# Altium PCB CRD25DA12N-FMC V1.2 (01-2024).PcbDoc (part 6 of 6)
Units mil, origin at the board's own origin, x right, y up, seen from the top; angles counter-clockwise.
Board outline 8000 x 8000 mil, 6 copper layers (Top Layer, Layer 2, Layer 3, Layer 4, Layer 5, Bottom Layer), stack 91 mil thick; 574 components, 325 nets, 1631 pads, 633 vias.
Unrouted connection lines stored in the file: 1.
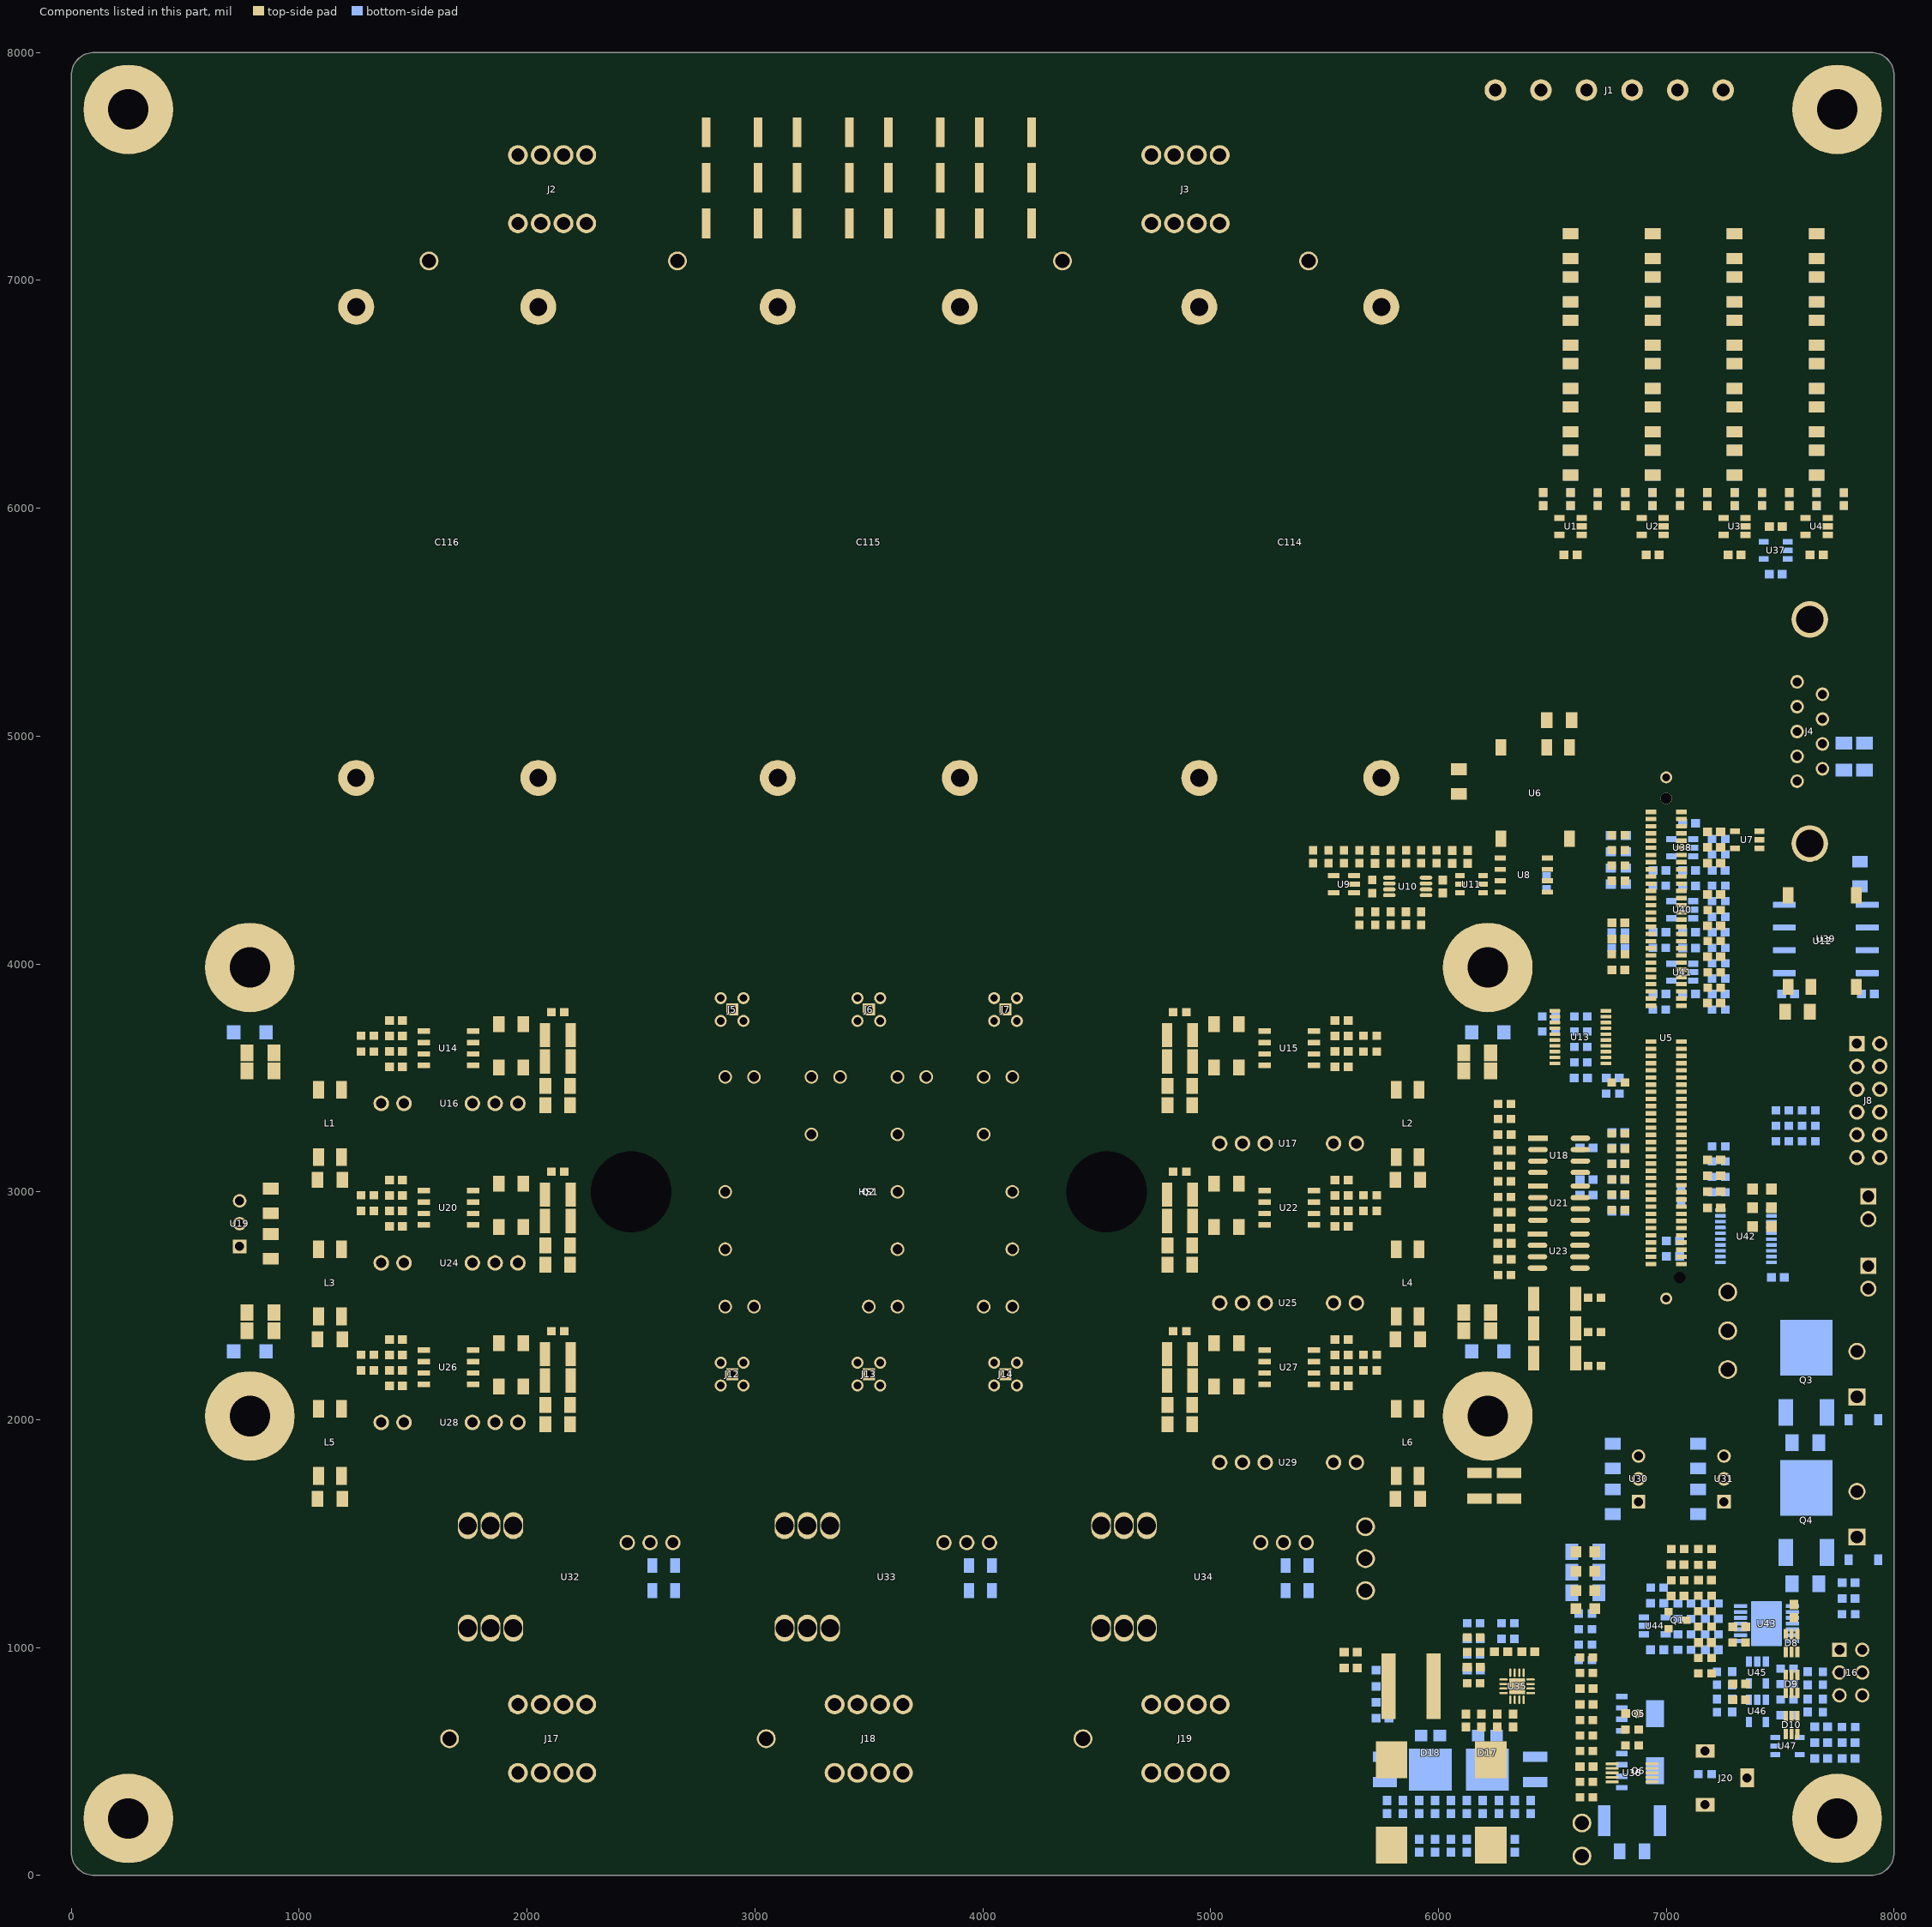
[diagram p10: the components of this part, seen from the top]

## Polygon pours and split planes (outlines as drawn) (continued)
NetC74_1 on Bottom Layer "NONET_L-01_P-001" (solid, pour order 964): 5535,2565 ccw(c5535,2520) 5490,2520 5490,2430 ccw(c5535,2430) 5535,2385 5715,2385 cw(c5715,2340) 5760,2340 5760,2335 ccw(c5805,2335) 5805,2290 5925,2290 ccw(c5925,2335) 5970,2335 5970,2345.83 cw(c6004.58,2350.42) 6000,2385 ccw(c5992.08,2417.08) 6025,2420 6025,2520 ccw(c5980,2520) 5980,2565
NetC49_1 on Bottom Layer "NONET_L-01_P-001" (solid, pour order 816): 5535,3265 ccw(c5535,3220) 5490,3220 5490,3130 ccw(c5535,3130) 5535,3085 5715,3085 cw(c5715,3040) 5760,3040 5760,3035 ccw(c5805,3035) 5805,2990 5925,2990 ccw(c5925,3035) 5970,3035 5970,3045.83 cw(c6004.58,3050.42) 6000,3085 ccw(c5992.08,3117.08) 6025,3120 6025,3220 ccw(c5980,3220) 5980,3265
S3 on Bottom Layer "Bottom Layer-S3" (solid, pour order 285): 21 vertices, not listed, extent 1830,3330 2225.07,3780
-3V_V_HS on Bottom Layer "Bottom Layer--3V_V_HS" (solid, pour order 1063): 1735,3374.9 ccw(c1780,3375) 1777.5,3330.07 ccw(c1775,3375) 1820,3374.91 1820,3415.4 1820.37,3415.77 cw(c1865,3410) 1859.85,3454.7 ccw(c1859.7,3500) 1905,3499.91 1905,3735.14 ccw(c1860,3735) 1860.23,3780 1779.81,3780 ccw(c1780,3735) 1735,3735 1735,3425
+15V_V_HS on Bottom Layer "Bottom Layer-+15V_V_HS" (solid, pour order 1062): 1980,3330 2005.11,3330 ccw(c2005,3375) 2050,3374.9 2050,3380.17 ccw(c2005,3380) 2005.11,3425 1979.86,3425 ccw(c1980,3380) 1935,3380 1935,3425 1935,3377.5 1935,3374.9 ccw(c1980,3375)
S2 on Bottom Layer "Bottom Layer-S2" (solid, pour order 1035): 21 vertices, not listed, extent 1830,1930 2225.07,2380
+15V_U_LS on Bottom Layer "Bottom Layer-+15V_U_LS" (solid, pour order 1030): 1980,1930 2005.11,1930 ccw(c2005,1975) 2050,1974.9 2050,1980.17 ccw(c2005,1980) 2005.11,2025 1979.86,2025 ccw(c1980,1980) 1935,1980 1935,2025 1935,1977.5 1935,1974.9 ccw(c1980,1975)
GND on Bottom Layer "Bottom Layer-GND 1" (solid, pour order 997): 6685,1694.87 ccw(c6730,1695) 6730,1650 6805,1650 6850,1695 6905,1695 ccw(c6904.9,1740.1) 6950,1740 ccw(c6904.88,1739.88) 6905,1785 6850,1785 6805,1830 6773.42,1830 6729.89,1830 ccw(c6730,1785) 6685,1785 6685,1745
+3.3V on Bottom Layer "Bottom Layer-+3.3V" (solid, pour order 985): 6855,1795 6905,1795 ccw(c6904.94,1840.06) 6950,1840 6950,1895 ccw(c6904.94,1894.94) 6905,1940 6729.86,1940 ccw(c6730,1895) 6685,1895 6685,1884.86 ccw(c6730,1885) 6730,1840 6810,1840
+12V on Bottom Layer "Bottom Layer-+12V" (solid, pour order 979): 6855,1685 6905,1685 cw(c6904.94,1639.94) 6950,1640 6950,1585 cw(c6904.94,1585.06) 6905,1540 6729.86,1540 cw(c6730,1585) 6685,1585 6685,1595.13 cw(c6730,1595) 6730,1640 6810,1640
+5V on Bottom Layer "Bottom Layer-+5V" (solid, pour order 978): 7230,1795 7280,1795 ccw(c7279.94,1840.06) 7325,1840 7325,1895 ccw(c7279.94,1894.94) 7280,1940 7104.86,1940 ccw(c7105,1895) 7060,1895 7060,1884.86 ccw(c7105,1885) 7105,1840 7185,1840
+12V on Bottom Layer "Bottom Layer-+12V 1" (solid, pour order 977): 7230,1685 7280,1685 cw(c7279.94,1639.94) 7325,1640 7325,1585 cw(c7279.94,1585.06) 7280,1540 7104.86,1540 cw(c7105,1585) 7060,1585 7060,1595.13 cw(c7105,1595) 7105,1640 7185,1640
GND on Bottom Layer "Bottom Layer-GND 1" (solid, pour order 975): 7060,1694.87 ccw(c7105,1695) 7105,1650 7180,1650 7225,1695 7280,1695 ccw(c7279.9,1740.1) 7325,1740 ccw(c7279.88,1739.88) 7280,1785 7225,1785 7180,1830 7148.42,1830 7104.89,1830 ccw(c7105,1785) 7060,1785 7060,1745
GND_ISO on Bottom Layer "Bottom Layer-GND_ISO" (solid, pour order 774): 7795,4405 7885,4405 7885,4480.14 ccw(c7840,4480) 7840,4525 7839.82,4525 ccw(c7840,4480) 7795,4480 7795,4415
GND_ISO on Bottom Layer "Bottom Layer-GND_ISO 1" (solid, pour order 765): 7905,4210 7950,4210 7950,4290 7795,4290 7795,4254.87 ccw(c7840,4255) 7840,4210 7905,4210
+5V_ISO on Bottom Layer "Bottom Layer-+5V_ISO" (solid, pour order 597): 7795,3855 ccw(c7840,3855) 7840,3810 7860,3810 7860,3940 7900,3940 7950,3940 7950,3965.13 ccw(c7905,3965) 7905,4010 7839.83,4010 ccw(c7840,3965) 7795,3965 7795,3900 7795,3870
GND_ISO on Bottom Layer "Bottom Layer-GND_ISO 2" (solid, pour order 521): 7905,3810 ccw(c7904.93,3855.07) 7950,3855 7950,3930 7870,3930 7870,3810
GND on Bottom Layer "GND_L06_P515" (solid, pour order 515): 7465,3935 7465,3775 7535,3775 7535,3935
+3.3V on Bottom Layer "+3.3V_L06_P306" (solid, pour order 306): 7605,3830 7605,3910 7585,3910 7585,4010 7465,4010 7465,3945 7540,3945 7540,3830
GND on Bottom Layer "GND_L06_P290" (solid, pour order 290): 7450,4295 7450,4210 7585,4210 7585,4295
GND on Layer 5 "Layer 5-GND" (solid, pour order 1966): 73 vertices, not listed, extent 2380,50 7950,6175
DC- on Layer 5 "Layer 3-DC-" (solid, pour order 2106): 57 vertices, not listed, extent 760,2878.55 6240,7740
W on Layer 5 "Layer 5-W" (solid, pour order 2040): 18 vertices, not listed, extent 4045.11,1000 4880.02,2775
V on Layer 5 "Layer 5-V" (solid, pour order 2038): 17 vertices, not listed, extent 2935,1000 3709.89,2775.01
U on Layer 5 "Layer 5-U" (solid, pour order 2036): 23 vertices, not listed, extent 1545,1000 2955,2775
GND_NTC on Layer 5 "Layer 2-GND_NTC" (solid, pour order 2107): 18 vertices, not listed, extent 5425,4140 6300,4995
GND on Layer 5 "Layer 5-GND 1" (solid, pour order 1849): 20 vertices, not listed, extent 490,1590 1575,3785
S3 on Layer 5 "Layer 5-S3" (solid, pour order 1929): 1780,3330 2180.14,3330 ccw(c2180,3375) 2225,3375 2225,3765.14 ccw(c2180,3765) 2180,3810 1779.86,3810 ccw(c1780,3765) 1735,3765 1735,3374.86 ccw(c1780,3375)
S5 on Layer 5 "Layer 5-S5" (solid, pour order 607): 4990,3780 4940,3780 4910,3810 4814.87,3810 ccw(c4815,3765) 4770,3765 4770,3349.83 ccw(c4815,3350) 4815,3305 4890,3305 5020,3175 5220.06,3175 ccw(c5220,3220) 5265,3220 5265,3725.1 ccw(c5220,3725) 5220,3770 5000,3770
S6 on Layer 5 "Layer 5-S6" (solid, pour order 1931): 4990,3080 4940,3080 4910,3110 4814.87,3110 ccw(c4815,3065) 4770,3065 4770,2649.83 ccw(c4815,2650) 4815,2605 4890,2605 5020,2475 5220.06,2475 ccw(c5220,2520) 5265,2520 5265,3025.1 ccw(c5220,3025) 5220,3070 5000,3070
S4 on Layer 5 "Layer 5-S4" (solid, pour order 1930): 4990,2380 4940,2380 4910,2410 4814.87,2410 ccw(c4815,2365) 4770,2365 4770,1949.83 ccw(c4815,1950) 4815,1905 4890,1905 5020,1775 5220.06,1775 ccw(c5220,1820) 5265,1820 5265,2325.1 ccw(c5220,2325) 5220,2370 5000,2370
S1 on Layer 5 "Layer 5-S1" (solid, pour order 1865): 1780,2630 2180.14,2630 ccw(c2180,2675) 2225,2675 2225,3065.14 ccw(c2180,3065) 2180,3110 1779.86,3110 ccw(c1780,3065) 1735,3065 1735,2674.86 ccw(c1780,2675)
S2 on Layer 5 "Layer 5-S2" (solid, pour order 1853): 1780,1930 2180.14,1930 ccw(c2180,1975) 2225,1975 2225,2365.14 ccw(c2180,2365) 2180,2410 1779.86,2410 ccw(c1780,2365) 1735,2365 1735,1974.86 ccw(c1780,1975)
GND_ISO on Layer 5 "Layer 2-GND_ISO" (solid, pour order 1068): 7720,4445 cw(c7718.14,4368.15) 7794.99,4366.29 7795,4365.13 7795,3855 ccw(c7840.04,3855.04) 7840.09,3810 7905.12,3810 ccw(c7905.06,3854.94) 7950,3855 7950,5523.95 ccw(c7879.48,5524.36) 7879.89,5594.88 7614.1,5594.88 ccw(c7611.97,5522.91) 7540,5525.04 7540,4515.03 ccw(c7610.02,4515.02) 7610.01,4445
GND on Top Layer "Top Layer-GND 8" (solid, pour order 2317): 6075,154.86 ccw(c6130,155) 6130,100 6165,100 6165,55 6295,55 6295,100 6350,100 ccw(c6350,155) 6405,155 6405,160.03 ccw(c6350,160) 6362.76,213.5 6117.24,213.5 ccw(c6130,160) 6075,160
-15V on Top Layer "Top Layer--15V" (solid, pour order 2271): 5565,95 ccw(c5610,95) 5610,50 5979.19,50.01 ccw(c5980,95) 6025,94.79 6025,164.59 ccw(c5980,165) 5979.63,210 5610,210 ccw(c5609.99,165.01) 5565,165 5565,95.13 ccw(c5608.24,95)
NetC109_2 on Top Layer "Top Layer-NetC202_2" (solid, pour order 2267): 6130,605 6215,605 6215,680 6055,680 6055,630 5763,630 5735,630 ccw(c5735,585) 5690,584.73 5690,554.81 ccw(c5735,555) 5735,510 5860,510 5860,535 6130,535
NetC111_2 on Top Layer "NONET_L-01_P-001" (solid, pour order 2115): 6140,595 6140,535 6385,535 6385,680 6230,680 6230,595
GND on Top Layer "NONET_L-01_P-001" (solid, pour order 2129): 6365,810 6365,740 6435,740 6435,810
NetC109_1 on Top Layer "NONET_L-01_P-001" (solid, pour order 2113): 5945,1000 5945,640 6040,640 6040,705 6350,705 6350,795 6305,795 6305,810 6100,810 6055,855 6055,1000
+12V on Top Layer "Top Layer-+12V 4" (solid, pour order 2263): 5690,685 ccw(c5735,685) 5735.13,640 5770.09,640 ccw(c5770,685) 5815,684.83 5814.99,1014.26 ccw(c5770,1015) 5770.13,1060 5735.26,1060 ccw(c5734.99,1015.01) 5690,1015 5690,1014.94 5690,685.65 ccw(c5733.98,685.01)
DC- on Top Layer "Top Layer-DC-" (solid, pour order 2292): 4265,2935 4265,2975.11 ccw(c4210,2975) 4208.55,3029.98 2789.73,3030 ccw(c2790,2975) 2735,2975 2735,2934.89 ccw(c2790,2935) 2788.99,2880.01 4210,2880 ccw(c4210,2935)
DC+ on Top Layer "Top Layer-DC+" (solid, pour order 2282): 2735.23,3240 ccw(c2790,3245) 2791.01,3190.01 4210,3190 ccw(c4210,3245) 4265,3245 4265,3260 ccw(c4210,3260) 4210,3315 2915,3315.02 2915,3290 2790,3290 ccw(c2790,3235)
+5V on Top Layer "Top Layer-+5V 1" (solid, pour order 2162): 17 vertices, not listed, extent 6755,615 7490,1940
GND on Top Layer "Top Layer-GND 5" (solid, pour order 1354): 6095.12,1615 cw(c6095,1640) 6070,1639.9 6070,1680.09 cw(c6095,1680) 6094.88,1705 6230,1705 6385.12,1705 cw(c6385,1680) 6410,1680.14 6410,1639.9 cw(c6385.12,1639.88) 6385.11,1615
G4 on Top Layer "Top Layer-G4" (solid, pour order 696): 23 vertices, not listed, extent 3605,1940 4870,2535
+12V on Top Layer "Top Layer-+12V 5" (solid, pour order 2080): 20 vertices, not listed, extent 675,3360 5880,4390
+15V_W_HS on Top Layer "Top Layer-+15V_W_HS 1" (solid, pour order 737): 5190,3675 5165,3700 5095,3700 5095,3770 5220.13,3770 cw(c5220,3725) 5265,3725 5265,3675
G5H on Top Layer "G5H_L01_P733" (solid, pour order 733): 4980,3752.79 4980,3690 5160,3690 5185,3665 5265,3665 5265,3635 4895,3635 4895,3752.8
G3 on Top Layer "Top Layer-G3" (solid, pour order 705): 25 vertices, not listed, extent 2130,3455 3405,4070
G5 on Top Layer "Top Layer-G5" (solid, pour order 706): 19 vertices, not listed, extent 3705,3465.25 4870,3805
G1 on Top Layer "Top Layer-G1" (solid, pour order 703): 2215,3085 2580,3450 2915,3450 2943.97,3450 2965.09,3450 ccw(c2965,3495) 3008.94,3485.28 3008.94,3560 2625,3560 2130,3065 2130,2810 2215,2810
G6 on Top Layer "Top Layer-G6" (solid, pour order 699): 4850,3060 4850,3100 4820,3100 4820,3060 4775,3060 4775,2900 4430,2555 3999.87,2555 ccw(c4000,2510) 3955,2510 3955,2489.84 ccw(c4000,2490) 4000,2445 4065,2445 4420,2445 4870,2895 4870,3060
G2 on Top Layer "Top Layer-G2" (solid, pour order 692): 2175,2350 2175,2400 2150,2400 2150,2350 2130,2350 2130,2110 2210,2110 2210,2210 2445,2445 2999.86,2445 ccw(c3000,2490) 3045,2490 3045,2510.16 ccw(c3000,2510) 3000,2555 2445,2555 2240,2350
+5V_NTC on Top Layer "Top Layer-+5V_NTC" (solid, pour order 1376): 18 vertices, not listed, extent 6055,4435 6300,4795
+5V_ISO on Top Layer "Top Layer-+5V_ISO" (solid, pour order 1576): 7829.79,4235.21 7883.86,4235.21 ccw(c7880,4270) 7915,4269.83 7915,4370.18 ccw(c7880,4370) 7880.19,4405 7829.79,4405 ccw(c7829.99,4370.01) 7795,4370.01 7795,4270 ccw(c7829.89,4270.1)
GND on Top Layer "Top Layer-GND 7" (solid, pour order 1568): 7465,3735 ccw(c7500,3735) 7499.85,3700 7540.15,3700 ccw(c7540,3735) 7575,3734.8 7575,3930.15 ccw(c7540,3930) 7540.17,3965 7499.83,3965 ccw(c7500,3930) 7465,3930.12
+3.3V on Top Layer "Top Layer-+3.3V" (solid, pour order 1560): 7585,3734.81 ccw(c7620,3735) 7619.85,3700 7640.17,3700 ccw(c7640,3735) 7675,3734.92 7675,3929.81 ccw(c7639.81,3929.81) 7640,3965 7619.76,3965 ccw(c7620,3930) 7585,3930.17
GND on Top Layer "Top Layer-GND" (solid, pour order 1476): 6590,4829.65 6600.17,4829.65 ccw(c6600,4874.65) 6645,4874.61 6645,5100 ccw(c6599.94,5099.94) 6600,5145 6590,5145 ccw(c6590.08,5099.92) 6545,5100 6545,4949.65 6545,4924.65 6545,4874.65 ccw(c6590,4874.65)
+3.3V on Top Layer "Top Layer-+5V" (solid, pour order 1377): 6450.39,4874.53 ccw(c6495.38,4874.65) 6492.89,4829.72 ccw(c6490.39,4874.65) 6535.39,4874.65 6535.39,5108.21 ccw(c6493.74,5102.96) 6490.91,5144.84 ccw(c6495.42,5100.04) 6450.39,5100
GND_NTC on Top Layer "Top Layer-GND_NTC" (solid, pour order 1373): 6100,4805 6214.09,4805 6255.11,4805 ccw(c6255,4849.99) 6300,4850 6300,4950.11 ccw(c6255.05,4950.05) 6255.11,4995 6100,4995 ccw(c6099.91,4950.09) 6055,4950 6055,4850 ccw(c6099.99,4849.99)
GND_ISO on Top Layer "Top Layer-GND_ISO" (solid, pour order 654): 7855,3810 7880,3810 7905.1,3810 ccw(c7905,3855) 7950,3854.9 7950,3965.17 ccw(c7905,3965) 7905.14,4010 7839.81,4010 ccw(c7840,3965) 7795,3965 7795,3854.86 ccw(c7840,3855) 7840,3810 7855,3810
+12V on Top Layer "Top Layer-+12V 2" (solid, pour order 796): 5870,3384.87 ccw(c5915,3385) 5915,3340 5915.17,3340 ccw(c5915,3385) 5960,3385 5960,3450 5960,3467.46 5960,3510 ccw(c5915,3510) 5915,3555 ccw(c5915.08,3509.92) 5870,3510 5870,3445
GND on Top Layer "Top Layer-+12V" (solid, pour order 879): 1040,3384.87 ccw(c1085,3385) 1085,3340 1085.16,3340 ccw(c1085,3385) 1130,3385 1130,3450 1130,3467.46 1130,3510 ccw(c1085,3510) 1085,3555 ccw(c1085.08,3509.92) 1040,3510 1040,3445
+15V_W_HS on Top Layer "Top Layer-+15V_W_HS" (solid, pour order 739): 5040.1,3180 ccw(c5040,3225) 5085,3225 5085,3370.17 ccw(c5040,3370) 5040,3415 4895,3415 4895,3310 5025,3180
+15V_W_LS on Top Layer "Top Layer-+15V_W_LS" (solid, pour order 747): 5040.1,2480 ccw(c5040,2525) 5085,2525 5085,2670.16 ccw(c5040,2670) 5040,2715 4895,2715 4895,2600 5015,2480
+15V_V_LS on Top Layer "Top Layer-+15V_V_LS" (solid, pour order 731): 5040.1,1780 ccw(c5040,1825) 5085,1825 5085,1970.16 ccw(c5040,1970) 5040,2015 4895,2015 4895,1900 5015,1780
GND on Top Layer "Top Layer-GND 6" (solid, pour order 1584): 6340,2235 ccw(c6375,2235) 6374.85,2200 6455.15,2200 ccw(c6455,2235) 6490,2234.83 6490,2565.17 ccw(c6455,2565) 6455.18,2600 6374.82,2600 ccw(c6375,2565) 6340,2565
NetHS1_3 on Top Layer "Top Layer-NetHS1_3" (solid, pour order 1333): 6315,1715 6365.13,1715 ccw(c6365,1760) 6410,1760 6410,2015 6070,2015 6070,1810 6070,1760 ccw(c6115,1760) 6115,1715 6180,1715
+15V_V_HS on Top Layer "Top Layer-+15V_V_HS" (solid, pour order 669): 19 vertices, not listed, extent 1735,3330 2110,3580
G3H on Top Layer "G3H_L01_P527" (solid, pour order 527): 1820,3590 2020,3590 2020,3510 2105,3510 2105,3625 1735,3625 1735,3590
NetC73_1 on Top Layer "Top Layer-NetC157_1" (solid, pour order 1244): 21 vertices, not listed, extent 1140,2290 1515,2740
NetC48_1 on Top Layer "Top Layer-NetC157_1" (solid, pour order 987): 21 vertices, not listed, extent 1140,2990 1515,3440
NetC91_1 on Top Layer "Top Layer-NetC157_1" (solid, pour order 874): 21 vertices, not listed, extent 1140,1590 1515,2040
NetC48_2 on Top Layer "Top Layer-NetC106_2" (solid, pour order 894): 1085,2990 ccw(c1087.43,3032.58) 1130,3030 1130,3105 1130,3280.13 ccw(c1085,3280) 1085,3325 1069.86,3325 ccw(c1069.92,3280.08) 1025,3280.13 1025,3215 1025,3030 ccw(c1077.84,3042.84) 1065,2990
+5V_ALT on Top Layer "Top Layer-+5V_ALT" (solid, pour order 986): 900,3075 cw(c900,3030) 945,3030.13 945,3010 cw(c899.94,3010.06) 900,2965 840,2965 835,2965 785,2915 715,2915 cw(c715.06,2960.06) 670,2960 670,3025 670,3030 cw(c715.07,3029.93) 715,3075
GND on Top Layer "Top Layer-GND 4" (solid, pour order 899): 18 vertices, not listed, extent 670,2770 945,2950
+12V on Top Layer "Top Layer-+12V 3" (solid, pour order 898): 900,2645 ccw(c900,2690) 945,2689.86 945,2710 ccw(c899.94,2709.94) 900,2755 840,2755 835,2755 785,2805 715,2805 ccw(c715.06,2759.94) 670,2760 670,2695 670,2690 ccw(c715.07,2690.07) 715,2645
+12V on Top Layer "Top Layer-+12V" (solid, pour order 877): 1140,3384.87 ccw(c1185,3385) 1185,3340 1185.16,3340 ccw(c1185,3385) 1230,3385 1230,3450 1230,3467.46 1230,3510 ccw(c1185,3510) 1185,3555 ccw(c1185.08,3509.92) 1140,3510 1140,3445
NetC91_2 on Top Layer "Top Layer-NetC157_2" (solid, pour order 876): 1085,1590 ccw(c1087.43,1632.58) 1130,1630 1130,1705 1130,1880.13 ccw(c1085,1880) 1085,1925 1069.86,1925 ccw(c1069.92,1880.08) 1025,1880.13 1025,1815 1025,1635 ccw(c1070,1635) 1070,1590
NetC73_2 on Top Layer "Top Layer-NetC136_2" (solid, pour order 873): 1085,2290 ccw(c1087.43,2332.58) 1130,2330 1130,2405 1130,2580.13 ccw(c1085,2580) 1085,2625 1069.86,2625 ccw(c1069.92,2580.08) 1025,2580.13 1025,2515 1025,2330 ccw(c1077.84,2342.84) 1065,2290
GND on Top Layer "Top Layer-+12V" (solid, pour order 872): 1040,2684.87 ccw(c1085,2685) 1085,2640 1085.16,2640 ccw(c1085,2685) 1130,2685 1130,2750 1130,2767.46 1130,2810 ccw(c1085,2810) 1085,2855 ccw(c1085.08,2809.92) 1040,2810 1040,2745
+12V on Top Layer "Top Layer-+12V" (solid, pour order 842): 1140,2684.87 ccw(c1185,2685) 1185,2640 1185.16,2640 ccw(c1185,2685) 1230,2685 1230,2750 1230,2767.46 1230,2810 ccw(c1185,2810) 1185,2855 ccw(c1185.08,2809.92) 1140,2810 1140,2745
GND on Top Layer "Top Layer-+12V" (solid, pour order 841): 1040,1984.87 ccw(c1085,1985) 1085,1940 1085.16,1940 ccw(c1085,1985) 1130,1985 1130,2050 1130,2067.46 1130,2110 ccw(c1085,2110) 1085,2155 ccw(c1085.08,2109.92) 1040,2110 1040,2045
+12V on Top Layer "Top Layer-+12V" (solid, pour order 840): 1140,1984.87 ccw(c1185,1985) 1185,1940 1185.16,1940 ccw(c1185,1985) 1230,1985 1230,2050 1230,2067.46 1230,2110 ccw(c1185,2110) 1185,2155 ccw(c1185.08,2109.92) 1140,2110 1140,2045
NetC92_1 on Top Layer "Top Layer-NetC156_1" (solid, pour order 839): 5970,1634.86 cw(c5924.96,1635.04) 5924.96,1590 5915,1590 cw(c5915.08,1635.08) 5870,1635 5870,1710 5870,1755 5870,1820.16 cw(c5915,1820) 5915,1865 5980,1865 cw(c5980,1820) 6025,1820.16 6025,1720 cw(c5992.54,1717.46) 5995,1685 ccw(c6007.84,1649.49) 5970.31,1645.31 5970,1640.19
NetC92_2 on Top Layer "Top Layer-NetC156_2" (solid, pour order 815): 22 vertices, not listed, extent 5490,1590 5860,1865
GND on Top Layer "Top Layer-GND 1" (solid, pour order 814): 5770,1984.87 ccw(c5815,1985) 5815,1940 5815.17,1940 ccw(c5815,1985) 5860,1985 5860,2050 5860,2067.46 5860,2110 ccw(c5815,2110) 5815,2155 ccw(c5815.08,2109.92) 5770,2110 5770,2045
+12V on Top Layer "Top Layer-+12V" (solid, pour order 813): 5870,1984.87 ccw(c5915,1985) 5915,1940 5915.17,1940 ccw(c5915,1985) 5960,1985 5960,2050 5960,2067.46 5960,2110 ccw(c5915,2110) 5915,2155 ccw(c5915.08,2109.92) 5870,2110 5870,2045
GND on Top Layer "Top Layer-GND 2" (solid, pour order 812): 5770,2684.87 ccw(c5815,2685) 5815,2640 5815.17,2640 ccw(c5815,2685) 5860,2685 5860,2750 5860,2767.46 5860,2810 ccw(c5815,2810) 5815,2855 ccw(c5815.08,2809.92) 5770,2810 5770,2745
+12V on Top Layer "Top Layer-+12V 1" (solid, pour order 811): 5870,2684.87 ccw(c5915,2685) 5915,2640 5915.17,2640 ccw(c5915,2685) 5960,2685 5960,2750 5960,2767.46 5960,2810 ccw(c5915,2810) 5915,2855 ccw(c5915.08,2809.92) 5870,2810 5870,2745
NetC74_1 on Top Layer "Top Layer-NetC135_1" (solid, pour order 810): 5970,2334.86 cw(c5924.96,2335.04) 5924.96,2290 5915,2290 cw(c5915.08,2335.08) 5870,2335 5870,2410 5870,2455 5870,2520.16 cw(c5915,2520) 5915,2565 5980,2565 cw(c5980,2520) 6025,2520.16 6025,2420 cw(c5992.54,2417.46) 5995,2385 ccw(c6007.84,2349.49) 5970.31,2345.31 5970,2340.19
NetC74_2 on Top Layer "Top Layer-NetC135_2" (solid, pour order 808): 22 vertices, not listed, extent 5490,2290 5860,2565
NetC49_1 on Top Layer "Top Layer-NetC105_1" (solid, pour order 807): 5970,3034.86 cw(c5924.96,3035.04) 5924.96,2990 5915,2990 cw(c5915.08,3035.08) 5870,3035 5870,3110 5870,3155 5870,3220.16 cw(c5915,3220) 5915,3265 5980,3265 cw(c5980,3220) 6025,3220.16 6025,3120 cw(c5992.54,3117.46) 5995,3085 ccw(c6007.84,3049.49) 5970.31,3045.31 5970,3040.19
NetC49_2 on Top Layer "Top Layer-NetC105_2" (solid, pour order 805): 22 vertices, not listed, extent 5490,2990 5860,3265
GND on Top Layer "Top Layer-GND 3" (solid, pour order 804): 5770,3384.87 ccw(c5815,3385) 5815,3340 5815.17,3340 ccw(c5815,3385) 5860,3385 5860,3450 5860,3467.46 5860,3510 ccw(c5815,3510) 5815,3555 ccw(c5815.08,3509.92) 5770,3510 5770,3445
-3V_W_LS on Top Layer "Top Layer--3V_W_LS" (solid, pour order 787): 21 vertices, not listed, extent 4895,2480.28 5265,2880
S6 on Top Layer "NONET_L-01_P-001" (solid, pour order 746): 4990,2880 4990,2810 5086.63,2810 5086.63,2880
+15V_W_LS on Top Layer "Top Layer-+15V_W_LS 1" (solid, pour order 745): 5190,2975 5165,3000 5095,3000 5095,3070 5220.13,3070 cw(c5220,3025) 5265,3025 5265,2975
S6 on Top Layer "NONET_L-01_P-001" (solid, pour order 744): 4785,2800 4785,2645 4880,2645 4880,2800
S6 on Top Layer "NONET_L-01_P-001" (solid, pour order 743): 4990,3070 4990,3000 5086.63,3000 5086.63,3070
G6L on Top Layer "G6L_L01_P742" (solid, pour order 742): 5180,2890 4980,2890 4980,2810 4895,2810 4895,2925 5265,2925 5265,2890
G6H on Top Layer "G6H_L01_P741" (solid, pour order 741): 4980,3052.79 4980,2990 5160,2990 5185,2965 5265,2965 5265,2935 4895,2935 4895,3052.8
-3V_W_HS on Top Layer "Top Layer--3V_W_HS" (solid, pour order 740): 21 vertices, not listed, extent 4895,3180.28 5265,3580
S5 on Top Layer "NONET_L-01_P-001" (solid, pour order 738): 4990,3580 4990,3510 5086.63,3510 5086.63,3580
S5 on Top Layer "NONET_L-01_P-001" (solid, pour order 736): 4785,3500 4785,3345 4880,3345 4880,3500
S5 on Top Layer "NONET_L-01_P-001" (solid, pour order 735): 4990,3770 4990,3700 5086.63,3700 5086.63,3770
G5L on Top Layer "G5L_L01_P734" (solid, pour order 734): 5180,3590 4980,3590 4980,3510 4895,3510 4895,3625 5265,3625 5265,3590
-3V_V_LS on Top Layer "Top Layer--3V_V_LS" (solid, pour order 732): 21 vertices, not listed, extent 4895,1780.28 5265,2180
S4 on Top Layer "NONET_L-01_P-001" (solid, pour order 725): 4990,2180 4990,2110 5086.63,2110 5086.63,2180
+15V_V_LS on Top Layer "Top Layer-+15V_V_LS 1" (solid, pour order 716): 5190,2275 5165,2300 5095,2300 5095,2370 5220.13,2370 cw(c5220,2325) 5265,2325 5265,2275
S4 on Top Layer "NONET_L-01_P-001" (solid, pour order 714): 4785,2100 4785,1945 4880,1945 4880,2100
S4 on Top Layer "NONET_L-01_P-001" (solid, pour order 713): 4990,2370 4990,2300 5086.63,2300 5086.63,2370
G4L on Top Layer "G4L_L01_P711" (solid, pour order 711): 5180,2190 4980,2190 4980,2110 4895,2110 4895,2225 5265,2225 5265,2190
G4H on Top Layer "G4H_L01_P710" (solid, pour order 710): 4980,2352.79 4980,2290 5160,2290 5185,2265 5265,2265 5265,2235 4895,2235 4895,2352.8
U_OUT on Top Layer "Layer 2-U_OUT" (solid, pour order 709): 25 vertices, not listed, extent 1545,340 2455,1620
W_OUT on Top Layer "Layer 2-W_OUT" (solid, pour order 708): 25 vertices, not listed, extent 4325,340 5235,1620
V_OUT on Top Layer "Layer 2-V_OUT" (solid, pour order 707): 25 vertices, not listed, extent 2935,340 3845,1620
+15V_U_LS on Top Layer "Top Layer-+15V_U_LS" (solid, pour order 688): 17 vertices, not listed, extent 1735,1930 2110,2180
-3V_U_LS on Top Layer "Top Layer--3V_U_LS" (solid, pour order 684): 1810,2275 1835,2300 1905,2300 1905,2370 1779.87,2370 ccw(c1780,2325) 1735,2325 1735,2275
S2 on Top Layer "NONET_L-01_P-001" (solid, pour order 683): 2010,2370 2010,2300 1913.37,2300 1913.37,2370
S2 on Top Layer "NONET_L-01_P-001" (solid, pour order 682): 2010,2180 2010,2110 1913.37,2110 1913.37,2180
-3V_U_LS on Top Layer "NONET_L-01_P-001" (solid, pour order 681): 2105,2100 2105,2030 2010,2030 2010,2100
S2 on Top Layer "NONET_L-01_P-001" (solid, pour order 680): 2215,2100 2215,1945 2120,1945 2120,2100
G2H on Top Layer "G2H_L01_P679" (solid, pour order 679): 1820,2190 2020,2190 2020,2110 2105,2110 2105,2225 1735,2225 1735,2190
G2L on Top Layer "G2L_L01_P678" (solid, pour order 678): 2020,2352.79 2020,2290 1840,2290 1815,2265 1735,2265 1735,2235 2105,2235 2105,2352.8
+15V_U_HS on Top Layer "Top Layer-+15V_U_HS" (solid, pour order 677): 19 vertices, not listed, extent 1735,2630 2110,2880
-3V_U_HS on Top Layer "Top Layer--3V_U_HS" (solid, pour order 676): 1810,2975 1835,3000 1905,3000 1905,3070 1779.87,3070 ccw(c1780,3025) 1735,3025 1735,2975
S1 on Top Layer "NONET_L-01_P-001" (solid, pour order 675): 2010,3070 2010,3000 1913.37,3000 1913.37,3070
S1 on Top Layer "NONET_L-01_P-001" (solid, pour order 674): 2010,2880 2010,2810 1913.37,2810 1913.37,2880
-3V_U_HS on Top Layer "NONET_L-01_P-001" (solid, pour order 673): 2105,2800 2105,2730 2010,2730 2010,2800
S1 on Top Layer "NONET_L-01_P-001" (solid, pour order 672): 2215,2800 2215,2645 2120,2645 2120,2800
G1H on Top Layer "G1H_L01_P671" (solid, pour order 671): 1820,2890 2020,2890 2020,2810 2105,2810 2105,2925 1735,2925 1735,2890
G1L on Top Layer "G1L_L01_P670" (solid, pour order 670): 2020,3052.79 2020,2990 1840,2990 1815,2965 1735,2965 1735,2935 2105,2935 2105,3052.8
S3 on Top Layer "NONET_L-01_P-001" (solid, pour order 658): 2010,3770 2010,3700 1913.37,3700 1913.37,3770
-3V_V_HS on Top Layer "Top Layer--3V_V_HS" (solid, pour order 668): 1810,3675 1835,3700 1905,3700 1905,3770 1779.87,3770 ccw(c1780,3725) 1735,3725 1735,3675
G3L on Top Layer "G3L_L01_P403" (solid, pour order 403): 2020,3752.79 2020,3690 1840,3690 1815,3665 1735,3665 1735,3635 2105,3635 2105,3752.8
S3 on Top Layer "NONET_L-01_P-001" (solid, pour order 657): 2010,3580 2010,3510 1913.37,3510 1913.37,3580
-3V_V_HS on Top Layer "NONET_L-01_P-001" (solid, pour order 656): 2105,3500 2105,3430 2010,3430 2010,3500
S3 on Top Layer "NONET_L-01_P-001" (solid, pour order 655): 2215,3500 2215,3345 2120,3345 2120,3500

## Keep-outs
Top Layer:
  lines w10: 3720.01,2054.2 ccw(c3770,2055) 3770.8,2005.01
Layer 2:
  circle w10: c7000,4726.18 r28.16
  circle w10: c7059.06,2623.82 r28.16
  lines w10: 1780,2315 1805,2315 ; 1780,3015 1805,3015 ; 1780,3715 1805,3715
Layer 3:
  circle w10: c7000,4726.18 r28.16
  circle w10: c7059.06,2623.82 r28.16
Layer 4:
  circle w10: c7000,4726.18 r28.16
  circle w10: c7059.06,2623.82 r28.16
Layer 5:
  circle w10: c7000,4726.18 r28.16
  circle w10: c7059.06,2623.82 r28.16

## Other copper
Layer 3:
  pour cut-out: 2787,3975 ccw(c2794.74,3905.26) 2725,3897.5 2725,3446.67 ccw(c2794.78,3444.78) 2792.89,3375 3040,3375 cw(c3040.01,3295.01) 3120,3295 3120,3195 ccw(c3190,3195) 3190,3125 4060,3125 ccw(c4060,3195) 4130,3195 4130,3300 cw(c4205,3300) 4205,3375 ccw(c4205,3445) 4275,3445 4275,3905 ccw(c4205.01,3905.01) 4205,3975
Layer 4:
  pour cut-out: 2787,3975 ccw(c2794.74,3905.26) 2725,3897.5 2725,3446.67 ccw(c2794.78,3444.78) 2792.89,3375 4204.85,3375 ccw(c4205,3445) 4275,3445 4275,3905 ccw(c4205.01,3905.01) 4205,3975
Layer 5:
  pour cut-out: 2787,3975 ccw(c2794.74,3905.26) 2725,3897.5 2725,3446.67 ccw(c2794.78,3444.78) 2792.89,3375 3040,3375 cw(c3040.01,3295.01) 3120,3295 3120,3195 ccw(c3190,3195) 3190,3125 4060,3125 ccw(c4060,3195) 4130,3195 4130,3300 cw(c4205,3300) 4205,3375 ccw(c4205,3445) 4275,3445 4275,3905 ccw(c4205.01,3905.01) 4205,3975
Bottom Layer:
  pour cut-out: 2820,4010 ccw(c2819.97,3890.02) 2700,3890 2700,3505 ccw(c2870,3505) 2870,3335 4135,3335 ccw(c4135.18,3499.82) 4300,3500 4300,3895 ccw(c4185.02,3895.02) 4185,4010

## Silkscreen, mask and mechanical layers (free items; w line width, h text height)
Top Overlay:
  drawing of 161 lines, arcs and shapes, not listed
  text "+" at 2026.69,7914.65 h250 r180
  text "-" at 4806.69,7914.96 h250 r180
  text "W-" at 6200.02,7585 h60
  text "W+" at 6400.02,7585 h60
  text "V-" at 6600.02,7585 h60
  text "V+" at 6800.02,7585 h60
  text "U-" at 7000.02,7585 h60
  text "U+" at 7200.02,7585 h60
  text "DC+" at 1490.03,7170 h60
  text "DC+" at 2580.03,7170 h60
  text "DC-" at 4270.03,7170 h60
  text "DC-" at 5350.03,7170 h60
  text "H" at 696.25,7076.88 h900
  text "CAUTION / HIGH VOLTAGE" at 660.11,7019.04 h60
  text "25kW WolfPACK FM3 Six-Pack Inverter / PN CRD25DA12N-FMC, V1.2 01/2024" at 1763.05,5355 h100
  text "U-HS / (G1)" at 2780.04,3880 h60
  text "V-HS / (G3)" at 3380.04,3880 h60
  text "W-HS / (G5)" at 3980.04,3880 h60
  text "(OFF)" at 2231,3647 h35
  text "(ON)" at 4658.2,3647 h35
  text "3.3" at 7546.26,3631 h35
  text "+5" at 7680.84,3631 h35
  text "PWR" at 7514,3555.7 h35 r90
  text "(ON)" at 2231,3531 h35
  text "(OFF)" at 4623.21,3531 h35
  text "GND" at 7543.35,3531 h35
  text "GND" at 7663.35,3531 h35
  text "A14" at 7546.26,3431 h35
  text "C14" at 7666.26,3431 h35
  text "ADC" at 7514,3405.7 h35 r90
  text "35" at 7560.84,3331 h35
  text "54" at 7680.84,3331 h35
  text "GPIO" at 7514,3243.77 h35 r90
  text "55" at 7560.84,3231 h35
  text "57" at 7680.84,3231 h35
  text "GND" at 7543.35,3131 h35
  text "+12" at 7666.26,3131 h35
  text "PWR" at 7514,3105.7 h35 r90
  text "+" at 7750,2950.01 h60 r90
  text "-" at 7749.99,2870.01 h60 r90
  text "12V" at 7724,2736.26 h35 r90
  text "(OFF)" at 2336,2706 h35
  text "(ON)" at 4553.2,2706 h35
  text "FANS" at 7655,2685.04 h60 r90
  text "+" at 7750,2645.01 h60 r90
  text "(ON)" at 2336,2591 h35
  text "(OFF)" at 4518.21,2591 h35
  text "-" at 7749.99,2565.01 h60 r90
  text "+3.3V" at 7350,2535 h60
  text "+5V" at 7350,2365 h60
  text "2-" at 7625,2250.02 h60 r90
  text "(OFF)" at 2231,2247 h35
  text "(ON)" at 4658.2,2247 h35
  text "GND" at 7350,2195 h60
  text "(ON)" at 2231,2131 h35
  text "(OFF)" at 4623.21,2131 h35
  text "2+" at 7625,2050.02 h60 r90
  text "U-LS / (G2)" at 2780.04,1944.04 h60
  text "V-LS / (G4)" at 3380.04,1944.04 h60
  text "W-LS / (G6)" at 3980.04,1944.04 h60
  text "RELAYS" at 7530,1725.06 h60 r90
  text "1-" at 7625,1640.01 h60 r90
  text "+15V" at 5770,1505 h60
  text "1+" at 7625,1440.01 h60 r90
  text "+3.3V" at 6250.09,1390 h60
  text "-15V" at 5770,1365 h60
  text "+5V" at 6360.05,1305 h60
  text "GND" at 5770,1225 h60
  text "+15V" at 6310.07,1220 h60
  text "-15V" at 6310.07,1140 h60
  text "U" at 1640.01,685 h60
  text "V" at 3030.01,685 h60
  text "W" at 4420.01,685 h60
  text "1" at 7499,534.17 h35 r90
  text "2" at 7564,528.34 h35 r90
  text "3" at 7499,478.34 h35 r90
  text "4" at 7564,478.34 h35 r90
  text "5" at 7499,428.34 h35 r90
  text "6" at 7564,428.34 h35 r90
  text "-" at 7465,364.99 h60 r180
  text "+12V" at 6720,205 h60
  text "+" at 7465,95 h60 r180
  text "U" at 2026.69,85 h250
  text "V" at 3416.69,85 h250
  text "W" at 4806.69,85 h250
  text "GND" at 6720,60 h60
  text "+12V" at 7496,16 h35
Bottom Overlay:
  lines w8: 6614.61,6089.61 6623.8,6098.8 ; 6974.61,6089.61 6983.8,6098.8 ; 7334.61,6089.61 7343.8,6098.8 ; 7694.61,6089.61 7703.8,6098.8 ; 7880,755 7880,669 7990,669 ; 7885,821 7992,821 7992,669
  lines w10: 5720,305 5740.39,305 ; 5790,130 5810.39,130 ; 6900,4015 6921.3,4036.3 6922.52,4036.3 ; 6900,4288 6921.3,4309.3 ; 6935,1300 6935,1350 ; 7080,1230 7080,1250 ; 7170,745 7185,745 ; 7170,865 7185,865 ; 7225,1230 7225,1250 ; 7315,465 7260,465 7260,635 7420,635 7420,465 7395,465 ; 7380,375 7380,360 7380,265 7540,265 ; 7395,435 7555,435 7555,330 ; 7420,620 7433.22,620 7482.52,669.3 ; 7510,3394 7510,3407 ; 7555,400 7632.5,477.5 ; 7625,3394 7625,3407 ; 7725,717.5 7874.5,717.5 ; 5135,195 5715,195 5715,375 5135,375 5135,195 ; 5315,15 5785,15 5785,195 5315,195 5315,15 ; 6580,3900 6900,3900 6900,4020 6580,4020 6580,3900 ; 6580,4183.5 6900,4183.5 6900,4303.5 6580,4303.5 6580,4183.5 ; 6832.5,1350 6997.5,1350 6997.5,1470 6832.5,1470 6832.5,1350 ; 7017.5,1250 7182.5,1250 7182.5,1470 7017.5,1470 7017.5,1250 ; 7050,600 7170,600 7170,765 7050,765 7050,600 ; 7050,780 7170,780 7170,940 7050,940 7050,780 ; 7202.5,1250 7367.5,1250 7367.5,1470 7202.5,1470 7202.5,1250 ; 7397.5,3407.5 7737.5,3407.5 7737.5,3572.5 7397.5,3572.5 7397.5,3407.5
Board Outline:
  lines w10: 55,-8425 ccw(c55,-8325) 155,-8325 ; 0,100 ccw(c100,100) 100,0 7900,0 ccw(c7900,100) 8000,100 8000,7900 ccw(c7900,7900) 7900,8000 100,8000 ccw(c100,7900) 0,7900 0,100
Drill Drawing:
  drawing of 185 lines, arcs and shapes, not listed
  text "*" at 140,12010 h60
  text "THESE HOLES (1.10MM +/- 0.05MM) ARE FOR PRESS-FIT PART. USE 47.2MIL +/- 1MIL DRILLED HOLES. COPPER THICKNESS IN HOLE 25-50UM." at 235,11955 h100
  text "w" at 9.31,11929.72 h200
  text "^" at 145,11825.01 h60
  text "THESE HOLES (1.48MM +/- 0.05MM) ARE FOR PRESS-FIT PART. USE 63.0MIL +/- 1MIL DRILLED HOLES. COPPER THICKNESS IN HOLE 25-60UM." at 240,11760 h100
  text "w" at 15.85,11741.66 h200
  text "Symbol" at 97.5,11578.94 h72
  text "Count" at 603.38,11578.94 h72
  text "Hole Size" at 1203.22,11578.94 h72
  text "Plated" at 2302.9,11578.94 h72
  text "Hole Type" at 2808.77,11578.94 h72
  text "Drill Layer Pair" at 3542.57,11578.94 h72
  text "Via/Pad" at 5042.13,11578.94 h72
  text "Pad Shape" at 5631.97,11578.94 h72
  text "Hole Tolerance (+)" at 6377.77,11578.94 h72
  text "Hole Tolerance (-)" at 7711.38,11578.94 h72
  text "Hole Length" at 9044.99,11578.94 h72
  text "Routed Path Length" at 10074.69,11578.94 h72
  text "20" at 603.38,11428.94 h60
  text "0.20mm (7.87mil)" at 1203.22,11428.94 h60
  text "PTH" at 2302.9,11428.94 h60
  text "Round" at 2808.77,11428.94 h60
  text "Top Layer - Bottom Layer" at 3542.57,11428.94 h60
  text "Via" at 5042.13,11428.94 h60
  text "Rounded" at 5631.97,11428.94 h60
  text "0.08mm (3.00mil)" at 6377.77,11428.94 h60
  text "0.08mm (3.00mil)" at 7711.38,11428.94 h60
  text "-" at 9044.99,11428.94 h60
  text "-" at 10074.69,11428.94 h60
  text "537" at 603.38,11278.94 h60
  text "0.33mm (13.00mil)" at 1203.22,11278.94 h60
  text "PTH" at 2302.9,11278.94 h60
  text "Round" at 2808.77,11278.94 h60
  text "Top Layer - Bottom Layer" at 3542.57,11278.94 h60
  text "Via" at 5042.13,11278.94 h60
  text "Rounded" at 5631.97,11278.94 h60
  text "0.08mm (3.00mil)" at 6377.77,11278.94 h60
  text "0.08mm (3.00mil)" at 7711.38,11278.94 h60
  text "-" at 9044.99,11278.94 h60
  text "-" at 10074.69,11278.94 h60
  text "A" at 68.41,11268.95 h66.67
  text "76" at 603.38,11128.94 h60
  text "0.71mm (28.00mil)" at 1203.22,11128.94 h60
  text "PTH" at 2302.9,11128.94 h60
  text "Round" at 2808.77,11128.94 h60
  text "Top Layer - Bottom Layer" at 3542.57,11128.94 h60
  text "Via" at 5042.13,11128.94 h60
  text "Rounded" at 5631.97,11128.94 h60
  text "0.08mm (3.00mil)" at 6377.77,11128.94 h60
  text "0.08mm (3.00mil)" at 7711.38,11128.94 h60
  text "-" at 9044.99,11128.94 h60
  text "-" at 10074.69,11128.94 h60
  text "32" at 603.38,10978.94 h60
  text "0.84mm (33.07mil)" at 1203.22,10978.94 h60
  text "PTH" at 2302.9,10978.94 h60
  text "Round" at 2808.77,10978.94 h60
  text "Top Layer - Bottom Layer" at 3542.57,10978.94 h60
  text "Pad" at 5042.13,10978.94 h60
  text "(Mixed)" at 5631.97,10978.94 h60
  text "0.08mm (3.00mil)" at 6377.77,10978.94 h60
  text "0.08mm (3.00mil)" at 7711.38,10978.94 h60
  text "-" at 9044.99,10978.94 h60
  text "-" at 10074.69,10978.94 h60
  text "18" at 603.38,10828.94 h60
  text "1.00mm (39.37mil)" at 1203.22,10828.94 h60
  text "PTH" at 2302.9,10828.94 h60
  text "Round" at 2808.77,10828.94 h60
  text "Top Layer - Bottom Layer" at 3542.57,10828.94 h60
  text "Pad" at 5042.13,10828.94 h60
  text "(Mixed)" at 5631.97,10828.94 h60
  text "0.08mm (3.00mil)" at 6377.77,10828.94 h60
  text "0.08mm (3.00mil)" at 7711.38,10828.94 h60
  text "-" at 9044.99,10828.94 h60
  text "-" at 10074.69,10828.94 h60
  text "3" at 603.38,10678.94 h60
  text "1.00mm (39.37mil)" at 1203.22,10678.94 h60
  text "PTH" at 2302.9,10678.94 h60
  text "Slot" at 2808.77,10678.94 h60
  text "Top Layer - Bottom Layer" at 3542.57,10678.94 h60
  text "Pad" at 5042.13,10678.94 h60
  text "Rectangle" at 5631.97,10678.94 h60
  text "0.08mm (3.00mil)" at 6377.77,10678.94 h60
  text "0.08mm (3.00mil)" at 7711.38,10678.94 h60
  text "1.60mm (62.99mil)" at 9044.99,10678.94 h60
  text "0.60mm (23.62mil)" at 10074.69,10678.94 h60
  text "B" at 68.41,10668.95 h66.67
  text "18" at 603.38,10528.94 h60
  text "1.10mm (43.31mil)" at 1203.22,10528.94 h60
  text "PTH" at 2302.9,10528.94 h60
  text "Round" at 2808.77,10528.94 h60
  text "Top Layer - Bottom Layer" at 3542.57,10528.94 h60
  text "Pad" at 5042.13,10528.94 h60
  text "(Mixed)" at 5631.97,10528.94 h60
  text "0.08mm (3.00mil)" at 6377.77,10528.94 h60
  text "0.08mm (3.00mil)" at 7711.38,10528.94 h60
  text "-" at 9044.99,10528.94 h60
  text "-" at 10074.69,10528.94 h60
  text "D" at 68.41,10518.95 h66.67
  text "*" at -85,10430 h60
  text "23" at 603.38,10378.94 h60
  text "1.10mm (43.31mil)" at 1203.22,10378.94 h60
  text "PTH" at 2302.9,10378.94 h60
  text "Round" at 2808.77,10378.94 h60
  text "Top Layer - Bottom Layer" at 3542.57,10378.94 h60
  text "Pad" at 5042.13,10378.94 h60
  text "Rounded" at 5631.97,10378.94 h60
  text "0.05mm (1.97mil)" at 6377.77,10378.94 h60
  text "0.05mm (1.97mil)" at 7711.38,10378.94 h60
  text "-" at 9044.99,10378.94 h60
  text "-" at 10074.69,10378.94 h60
  text "w" at -215.69,10349.72 h200
  text "30" at 603.38,10228.94 h60
  text "1.15mm (45.28mil)" at 1203.22,10228.94 h60
  text "PTH" at 2302.9,10228.94 h60
  text "Round" at 2808.77,10228.94 h60
  text "Top Layer - Bottom Layer" at 3542.57,10228.94 h60
  text "Pad" at 5042.13,10228.94 h60
  text "Rounded" at 5631.97,10228.94 h60
  text "0.08mm (3.00mil)" at 6377.77,10228.94 h60
  text "0.08mm (3.00mil)" at 7711.38,10228.94 h60
  text "-" at 9044.99,10228.94 h60
  text "-" at 10074.69,10228.94 h60
  text "9" at 603.38,10078.94 h60
  text "1.20mm (47.24mil)" at 1203.22,10078.94 h60
  text "PTH" at 2302.9,10078.94 h60
  text "Round" at 2808.77,10078.94 h60
  text "Top Layer - Bottom Layer" at 3542.57,10078.94 h60
  text "Pad" at 5042.13,10078.94 h60
  text "Rounded" at 5631.97,10078.94 h60
  text "0.08mm (3.00mil)" at 6377.77,10078.94 h60
  text "0.08mm (3.00mil)" at 7711.38,10078.94 h60
  text "-" at 9044.99,10078.94 h60
  text "-" at 10074.69,10078.94 h60
  text "2" at 603.38,9928.94 h60
  text "1.27mm (50.00mil)" at 1203.22,9928.94 h60
  text "NPTH" at 2302.9,9928.94 h60
  text "Round" at 2808.77,9928.94 h60
  text "Top Layer - Bottom Layer" at 3542.57,9928.94 h60
  text "Pad" at 5042.13,9928.94 h60
  text "Rounded" at 5631.97,9928.94 h60
  text "0.08mm (3.00mil)" at 6377.77,9928.94 h60
  text "0.08mm (3.00mil)" at 7711.38,9928.94 h60
  text "-" at 9044.99,9928.94 h60
  text "-" at 10074.69,9928.94 h60
  text "4" at 603.38,9778.94 h60
  text "1.30mm (51.18mil)" at 1203.22,9778.94 h60
  text "PTH" at 2302.9,9778.94 h60
  text "Round" at 2808.77,9778.94 h60
  text "Top Layer - Bottom Layer" at 3542.57,9778.94 h60
  text "Pad" at 5042.13,9778.94 h60
  text "(Mixed)" at 5631.97,9778.94 h60
  text "0.08mm (3.00mil)" at 6377.77,9778.94 h60
  text "0.08mm (3.00mil)" at 7711.38,9778.94 h60
  text "-" at 9044.99,9778.94 h60
  text "-" at 10074.69,9778.94 h60
  text "C" at 68.41,9768.95 h66.67
  text "10" at 603.38,9628.94 h60
  text "1.40mm (55.12mil)" at 1203.22,9628.94 h60
  text "PTH" at 2302.9,9628.94 h60
  text "Round" at 2808.77,9628.94 h60
  text "Top Layer - Bottom Layer" at 3542.57,9628.94 h60
  text "Pad" at 5042.13,9628.94 h60
  text "(Mixed)" at 5631.97,9628.94 h60
  text "0.08mm (3.00mil)" at 6377.77,9628.94 h60
  text "0.08mm (3.00mil)" at 7711.38,9628.94 h60
  text "-" at 9044.99,9628.94 h60
  text "-" at 10074.69,9628.94 h60
  text "^" at -100,9525.01 h60
  text "40" at 603.38,9478.94 h60
  text "1.48mm (58.07mil)" at 1203.22,9478.94 h60
  text "PTH" at 2302.9,9478.94 h60
  text "Round" at 2808.77,9478.94 h60
  text "Top Layer - Bottom Layer" at 3542.57,9478.94 h60
  text "Pad" at 5042.13,9478.94 h60
  text "Rounded" at 5631.97,9478.94 h60
  text "0.05mm (1.97mil)" at 6377.77,9478.94 h60
  text "0.05mm (1.97mil)" at 7711.38,9478.94 h60
  text "-" at 9044.99,9478.94 h60
  text "-" at 10074.69,9478.94 h60
  text "E" at 68.41,9468.95 h66.67
  text "w" at -229.15,9441.66 h200
  text "15" at 603.38,9328.94 h60
  text "1.60mm (62.99mil)" at 1203.22,9328.94 h60
  text "PTH" at 2302.9,9328.94 h60
  text "Round" at 2808.77,9328.94 h60
  text "Top Layer - Bottom Layer" at 3542.57,9328.94 h60
  text "Pad" at 5042.13,9328.94 h60
  text "Rounded" at 5631.97,9328.94 h60
  text "0.08mm (3.00mil)" at 6377.77,9328.94 h60
  text "0.08mm (3.00mil)" at 7711.38,9328.94 h60
  text "-" at 9044.99,9328.94 h60
  text "-" at 10074.69,9328.94 h60
  text "30" at 603.38,9178.94 h60
  text "2.00mm (78.74mil)" at 1203.22,9178.94 h60
  text "PTH" at 2302.9,9178.94 h60
  text "Round" at 2808.77,9178.94 h60
  text "Top Layer - Bottom Layer" at 3542.57,9178.94 h60
  text "Pad" at 5042.13,9178.94 h60
  text "Rounded" at 5631.97,9178.94 h60
  text "0.08mm (3.00mil)" at 6377.77,9178.94 h60
  text "0.08mm (3.00mil)" at 7711.38,9178.94 h60
  text "-" at 9044.99,9178.94 h60
  text "-" at 10074.69,9178.94 h60
  text "2" at 603.38,9028.94 h60
  text "3.05mm (120.08mil)" at 1203.22,9028.94 h60
  text "PTH" at 2302.9,9028.94 h60
  text "Round" at 2808.77,9028.94 h60
  text "Top Layer - Bottom Layer" at 3542.57,9028.94 h60
  text "Pad" at 5042.13,9028.94 h60
  text "Rounded" at 5631.97,9028.94 h60
  text "0.13mm (5.00mil)" at 6377.77,9028.94 h60
  text "0.13mm (5.00mil)" at 7711.38,9028.94 h60
  text "-" at 9044.99,9028.94 h60
  text "-" at 10074.69,9028.94 h60
  text "8" at 603.38,8878.94 h60
  text "4.50mm (177.17mil)" at 1203.22,8878.94 h60
  text "PTH" at 2302.9,8878.94 h60
  text "Round" at 2808.77,8878.94 h60
  text "Top Layer - Bottom Layer" at 3542.57,8878.94 h60
  text "Pad" at 5042.13,8878.94 h60
  text "Rounded" at 5631.97,8878.94 h60
  text "0.13mm (5.00mil)" at 6377.77,8878.94 h60
  text "0.13mm (5.00mil)" at 7711.38,8878.94 h60
  text "-" at 9044.99,8878.94 h60
  text "-" at 10074.69,8878.94 h60
  text "2" at 603.38,8728.94 h60
  text "9.00mm (354.33mil)" at 1203.22,8728.94 h60
  text "NPTH" at 2302.9,8728.94 h60
  text "Round" at 2808.77,8728.94 h60
  text "Top Layer - Bottom Layer" at 3542.57,8728.94 h60
  text "Pad" at 5042.13,8728.94 h60
  text "Rounded" at 5631.97,8728.94 h60
  text "0.13mm (5.00mil)" at 6377.77,8728.94 h60
  text "0.13mm (5.00mil)" at 7711.38,8728.94 h60
  text "-" at 9044.99,8728.94 h60
  text "-" at 10074.69,8728.94 h60
  text "F" at 68.41,8718.95 h66.67
  text "879 Total" at 603.38,8578.94 h60
  text "Slot definitions :" at 97.5,8433.97 h60
  text "Routed Path Length" at 1130.19,8433.97 h60
  text "= Calculated from tool start centre position to tool end centre position." at 2232.86,8433.97 h60
  text "Hole Length" at 1130.19,8333.99 h60
  text "= Routed Path Length + Tool Size = Slot length as defined in the PCB layout" at 1822.99,8333.99 h60

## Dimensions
100,8000 to 100,0 on Drill Drawing
0,100 to 8000,100 on Drill Drawing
